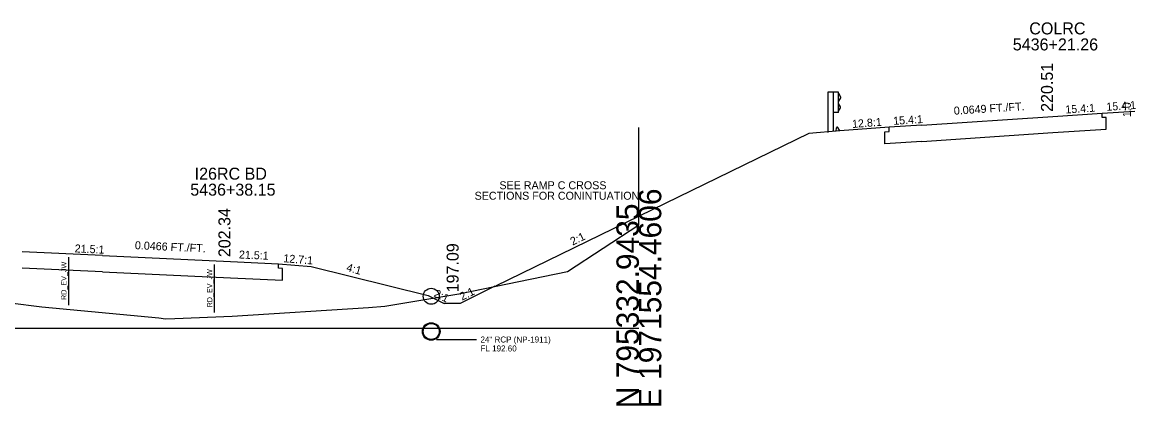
# Model space of a CAD drawing. Extents: x -161 to 1970889, y -4362 to 797231.
# Drawn here: x 1223 to 1362.1, y 2990.3 to 3038.3 of the extents above; entities that cross this region are included whole.
import ezdxf

# ---------------------------------------------------------------- set-up
doc = ezdxf.new("R2010")
doc.units = 0
for name, color, linetype in [('RD_GPK_XS_Cell', 7, 'Continuous'), ('RD_XS_Base', 7, 'Continuous'), ('RD_XS_CurbTop', 7, 'Continuous'), ('RD_XS_EarthShd', 7, 'Continuous'), ('RD_XS_ExGround', 7, 'Continuous'), ('RD_XS_EXWetland', 7, 'Continuous'), ('RD_XS_GR', 7, 'Continuous'), ('RD_XS_Pave', 7, 'Continuous'), ('RD_XS_PaveShd', 7, 'Continuous'), ('RD_XS_Pipe', 7, 'Continuous'), ('RD_XS_TieSlope', 7, 'Continuous'), ('RD_XS_TX_Elev_PR', 7, 'Continuous'), ('RD_XS_TX_Misc', 7, 'Continuous'), ('RD_XS_TX_Notes', 7, 'Continuous'), ('RD_XS_TX_Profile', 7, 'Continuous'), ('RD_XS_TX_ShdSlope', 7, 'Continuous'), ('RD_XS_TX_Slope', 7, 'Continuous'), ('RD_XS_TX_Station', 7, 'Continuous')]:
    doc.layers.add(name, color=color, linetype=linetype)

msp = doc.modelspace()

# ---------------------------------------------------------------- linework, layer by layer
at = {"layer": 'RD_GPK_XS_Cell'}
msp.add_line((1150, 3000), (1300, 3000), dxfattribs=at)
at = {"layer": 'RD_XS_Base'}
for p, q in [((1357.87, 3026.35), (1357.87, 3026.91)), ((1331.25, 3024.6), (1331.25, 3025.16)), ((1358.38, 3026.38), (1357.87, 3026.35)), ((1358.38, 3024.9), (1358.38, 3026.38)), ((1330.73, 3024.56), (1331.25, 3024.6)), ((1330.73, 3023.08), (1330.73, 3024.56)), ((1335.34, 3023.38), (1351.73, 3024.47)), ((1351.73, 3024.47), (1358.38, 3024.9)), ((1335.34, 3023.38), (1330.73, 3023.08)), ((1232.98, 3007.05), (1222.98, 3007.51)), ((1254.98, 3007.5), (1254.98, 3008.06)), ((1255.48, 3007.48), (1254.98, 3007.5)), ((1255.48, 3006), (1255.48, 3007.48)), ((1232.98, 3007.05), (1248.98, 3006.3)), ((1248.98, 3006.3), (1255.48, 3006))]:
    msp.add_line(p, q, dxfattribs=at)
at = {"layer": 'RD_XS_CurbTop'}
for p, q in [((1324.63, 3024.64), (1324.69, 3025.07)), ((1325.1, 3024.68), (1324.63, 3024.64)), ((1325.1, 3024.68), (1324.85, 3025.13))]:
    msp.add_line(p, q, dxfattribs=at)
msp.add_ellipse((1324.78, 3025.05), major_axis=(0, 0.131), ratio=0.686, start_param=5.388101, end_param=7.661995, dxfattribs=at)
at = {"layer": 'RD_XS_EarthShd'}
for p, q in [((1357.87, 3026.91), (1361.96, 3027.18)), ((1331.25, 3025.16), (1325.1, 3024.68)), ((1254.98, 3008.06), (1259.06, 3007.74))]:
    msp.add_line(p, q, dxfattribs=at)
at = {"layer": 'RD_XS_ExGround'}
msp.add_lwpolyline([(1221.47, 3003.19), (1225.42, 3002.68), (1240.03, 3001.29), (1240.85, 3001.19), (1242.04, 3001.23), (1249.2, 3001.52), (1266.23, 3002.6), (1268.27, 3002.75), (1277.5, 3004.32), (1291.09, 3007.11), (1300, 3012.92)], dxfattribs=at)
at = {"layer": 'RD_XS_EXWetland'}
for p, q in [((1228.75, 3008.9), (1228.75, 3002.9)), ((1246.96, 3007.97), (1246.96, 3001.97))]:
    msp.add_line(p, q, dxfattribs=at)
at = {"layer": 'RD_XS_GR'}
for p, q in [((1324.26, 3029.55), (1323.6, 3029.55)), ((1323.6, 3029.55), (1323.6, 3024.5)), ((1324.93, 3029.55), (1324.26, 3029.55)), ((1324.26, 3029.55), (1324.26, 3024.61)), ((1324.93, 3026.98), (1324.93, 3029.55)), ((1324.93, 3029.39), (1325.2, 3028.95)), ((1325.2, 3028.84), (1324.93, 3028.4)), ((1325.2, 3027.69), (1324.93, 3028.13)), ((1325.2, 3028.95), (1325.2, 3028.84)), ((1324.93, 3026.98), (1324.26, 3026.98)), ((1324.93, 3027.14), (1325.2, 3027.58)), ((1325.2, 3027.58), (1325.2, 3027.69))]:
    msp.add_line(p, q, dxfattribs=at)
at = {"layer": 'RD_XS_Pave'}
for p, q in [((1335.34, 3025.42), (1351.73, 3026.51)), ((1232.98, 3009.09), (1248.98, 3008.34))]:
    msp.add_line(p, q, dxfattribs=at)
at = {"layer": 'RD_XS_PaveShd'}
for p, q in [((1351.73, 3026.51), (1357.87, 3026.91)), ((1335.34, 3025.42), (1331.25, 3025.16)), ((1232.98, 3009.09), (1222.98, 3009.55)), ((1248.98, 3008.34), (1254.98, 3008.06))]:
    msp.add_line(p, q, dxfattribs=at)
at = {"layer": 'RD_XS_Pipe'}
msp.add_line((1274.72, 2998.6), (1279.72, 2998.6), dxfattribs=at)
for centre, radius in [((1274.06, 3004), 1), ((1274.06, 2999.6), 1.1), ((1274.06, 2999.6), 1)]:
    msp.add_circle(centre, radius, dxfattribs=at)
at = {"layer": 'RD_XS_TieSlope'}
for p, q in [((1321.25, 3024.38), (1282.09, 3005.27)), ((1325.1, 3024.68), (1321.25, 3024.38)), ((1259.06, 3007.74), (1273.68, 3004.09)), ((1281.99, 3005.25), (1277.68, 3003.09)), ((1273.68, 3004.09), (1275.68, 3003.09)), ((1277.68, 3003.09), (1275.68, 3003.09))]:
    msp.add_line(p, q, dxfattribs=at)
at = {"layer": 'RD_XS_TX_Notes'}
msp.add_line((1300, 3012.92), (1300, 3025.13), dxfattribs=at)

# ---------------------------------------------------------------- texts
at = {"layer": 'RD_GPK_XS_Cell'}
for s, p in [('E 1971554.4606', (1302.8, 2990)), ('N 795332.9435', (1300, 2990))]:
    msp.add_text(s, height=2.8, rotation=90, dxfattribs=at).set_placement(p)
at = {"layer": 'RD_XS_EXWetland'}
for p in [(1228.5, 3003.54), (1246.71, 3002.61)]:
    msp.add_text('RD_EV_JW', height=0.65, rotation=90, dxfattribs=at).set_placement(p)
at = {"layer": 'RD_XS_Pipe'}
for s, p in [('24" RCP (NP-1911)', (1280.22, 2998.22)), ('FL 192.60', (1280.22, 2997.1))]:
    msp.add_text(s, height=0.75, dxfattribs=at).set_placement(p)
at = {"layer": 'RD_XS_TX_Elev_PR'}
for s, p in [(' 220.51', (1351.73, 3026.51)), (' 202.34', (1248.98, 3008.34))]:
    msp.add_text(s, height=1.5, rotation=90, dxfattribs=at).set_placement(p)
at = {"layer": 'RD_XS_TX_Misc'}
msp.add_text('197.09', height=1.5, rotation=90, dxfattribs=at).set_placement((1277.49, 3004.5))
at = {"layer": 'RD_XS_TX_Notes'}
for s, p in [('SEE RAMP C CROSS ', (1282.58, 3017.39)), ('SECTIONS FOR CONINTUATION', (1279.48, 3016.08))]:
    msp.add_text(s, height=1, rotation=360, dxfattribs=at).set_placement(p)
at = {"layer": 'RD_XS_TX_Profile'}
msp.add_text('21.5:1', height=1, rotation=357.3311, dxfattribs=at).set_placement((1250.02, 3008.74))
at = {"layer": 'RD_XS_TX_ShdSlope'}
for s, rotation, p in [('15.4:1', 3.7194, (1358.42, 3027.2)), ('12.8:1', 4.4643, (1326.67, 3025.05)), ('12.7:1', 355.512, (1255.56, 3008.27))]:
    msp.add_text(s, height=1, rotation=rotation, dxfattribs=at).set_placement(p)
at = {"layer": 'RD_XS_TX_Slope'}
for s, rotation, p in [('0.0649 FT./FT.', 3.7148, (1339.37, 3026.71)), ('15.4:1', 3.7194, (1353.3, 3026.86)), ('1:0', 90, (1361.46, 3026.41)), ('15.4:1', 3.7148, (1331.8, 3025.44)), ('2:1', 26.0108, (1291.73, 3010.34)), ('21.5:1', 357.3311, (1229.51, 3009.5)), ('0.0466 FT./FT.', 357.3311, (1237.03, 3009.9)), ('4:1', 344.1175, (1263.39, 3007.19)), ('2:1', 333.5094, (1274.3, 3004.02)), ('2:1', 26.5651, (1277.92, 3003.45))]:
    msp.add_text(s, height=1, rotation=rotation, dxfattribs=at).set_placement(p)
at = {"layer": 'RD_XS_TX_Station'}
for s, p in [('COLRC', (1348.77, 3036.76)), ('5436+21.26', (1346.71, 3034.76)), ('I26RC BD', (1244.51, 3018.59)), ('5436+38.15', (1243.96, 3016.59))]:
    msp.add_text(s, height=1.5, dxfattribs=at).set_placement(p)

doc.saveas('drawing.dxf')
